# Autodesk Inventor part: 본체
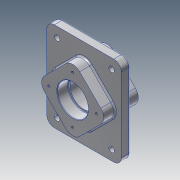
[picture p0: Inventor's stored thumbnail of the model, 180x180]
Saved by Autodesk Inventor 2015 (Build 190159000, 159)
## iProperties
Created: 2026-07
Part Number: 본체
Material: 알루미늄 6061
Document SubType Name: Modeling
Designer: USER
Density: 2.7 g/cm^3
Appearance: 알루미늄 - 평지
Mass: 2132.41 g
Surface Area: 955.114 cm^2
Volume: 789.782 cm^3
Author: USER
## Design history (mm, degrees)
sketch "스케치1"
  geometry: L1 (60, 90)-(-60, 90); L2 (-75, 75)-(-75, -75); L3 (-60, -90)-(60, -90); L4 (75, -75)-(75, 75); L5 (75, 90)-(-75, -90); L6 (-75, 90)-(75, -90); A1 r 15 centre (60, 75) between (75, 75) and (60, 90); A2 r 15 centre (-60, 75) between (-60, 90) and (-75, 75); A3 r 15 centre (-60, -75) between (-75, -75) and (-60, -90); A4 r 15 centre (60, -75) between (60, -90) and (75, -75); 1 further point
  constraints: 12 end point, 8 point on circle, 8 point on line, 8 tangent, 4 centre point, 3 equal radius, 2 midpoint, 2 parallel, 1 horizontal, 1 perpendicular
  dimensions: "d0" = 150 distance of L6.end L5.end; "d1" = 180 distance of L5.end L6.start; "d2" = 15 radius of A1
extrude "돌출1" new body sketch "스케치1" stored distance "d3" = 18; taper "d4" = 0 deg
sketch "스케치3"
  geometry: L1 (-14.142, -56.569)-(-56.569, -14.142); L2 (-56.569, 14.142)-(-14.142, 56.569); L3 (14.142, 56.569)-(56.569, 14.142); L4 (56.569, -14.142)-(14.142, -56.569); A1 r 20 centre (-42.426, 0) between (-56.569, 14.142) and (-56.569, -14.142); A2 r 20 centre (0, 42.426) between (14.142, 56.569) and (-14.142, 56.569); A3 r 20 centre (42.426, 0) between (56.569, -14.142) and (56.569, 14.142); A4 r 20 centre (0, -42.426) between (-14.142, -56.569) and (14.142, -56.569); 6 further points
  constraints: 8 end point, 8 point on circle, 8 point on line, 8 tangent, 4 centre point, 3 equal radius, 1 coincident, 1 vertical alignment, 9 other
  dimensions: "d6" = 100 distance of point (0, 70.711) point (70.711, 0); "d11" = 20 radius of A1
extrude "돌출2" join sketch "스케치3" distance "d7" = 23; taper "d9" = 0 deg; dims "d8" = 47, "d10" = 0
sketch "스케치4"
  geometry: L1 (-60, -90)-(60, -90) reference; L2 (-75, 75)-(-75, -75) reference; C1 r 11 at (-54.5, -70); 1 further point
  constraints: 1 centre point
  dimensions: "d12" = 22 diameter of C1; "d13" = 20 distance from line of L1 C1.centre; "d14" = 20.5 distance from line of C1.centre L2
extrude "돌출3" join sketch "스케치4" distance "d15" = 5; taper "d16" = 0 deg
hole "구멍1" diameter "d19" = 11; stored, may be unused: countersink angle "d23" = 90 deg, drill point angle "d25" = 118 deg; dims "d17" = 10, "d18" = 10, "d20" = 6, "d21" = 4, "d22" = 2, "d24" = 8
sketch "스케치5"
  geometry: C1 r 31 at (0, 0); 1 further point
  constraints: 1 centre point, 1 coincident
  dimensions: "d32" = 62 diameter of C1
extrude "돌출4" cut sketch "스케치5" distance "d33" = 22; taper "d34" = 0 deg
hole "구멍2" diameter "d37" = 54; stored, may be unused: countersink angle "d41" = 90 deg, drill point angle "d43" = 118 deg; dims "d35" = 50, "d36" = 50, "d38" = 6, "d39" = 62, "d40" = 22, "d42" = 8
sketch "스케치6"
  geometry: L1 (0, 0)-(0, 48); C1 r 27 at (0, 0) reference; 1 further point
  constraints: 2 end point, 1 vertical
  dimensions: "d44" = 48 distance of L1.start L1.end
hole "구멍3" sketch "스케치6" at (0, 48) diameter "d45" = 4.917; stored, may be unused: countersink angle "d49" = 90 deg, drill point angle "d51" = 118 deg; dims "d46" = 10, "d47" = 62, "d48" = 22, "d50" = 13
sketch "스케치7"
  geometry: L1 (0, 0)-(0, -48); C1 r 2.458 at (0, -48) reference
  constraints: 2 end point, 1 vertical
  dimensions: "d55" = 48 distance of L1.start L1.end (derived)
hole "구멍4" sketch "스케치7" at (0, -48) diameter "d56" = 4.917; stored, may be unused: countersink angle "d60" = 90 deg, drill point angle "d62" = 118 deg; dims "d57" = 10, "d58" = 62, "d59" = 22, "d61" = 13
sketch "스케치8"
  geometry: L1 (-60, -90)-(60, -90) reference; 3 further points
  constraints: 1 midpoint, 1 vertical alignment, 1 other
  dimensions: "d66" = 15 distance of point (0, -75) point (0, -90)
feature "엠보싱1" sketch "스케치8" dims "d0" = 150, "d1" = 180, "d2" = 15, "d67" = 0.5, "d68" = 0
chamfer "모따기1" distance "d69" = 1; stored, may be unused: second distance "d70" = 2, angle "d71" = 45 deg
fillet "모깎기1" dims "d72" = 1
fillet "모깎기2" dims "d73" = 3
node "솔리드1"
pattern_linear "직사각형 패턴1"
pattern_circular "원형 패턴1" dims angle "d53" = 360 deg
pattern_circular "원형 패턴2" dims angle "d64" = 360 deg
